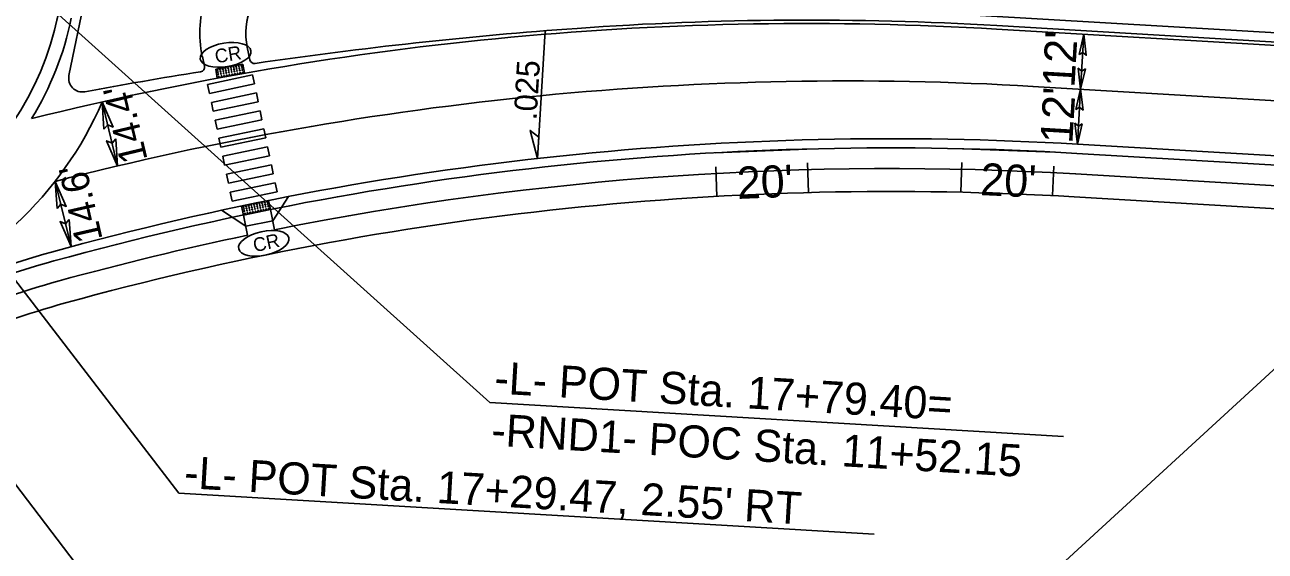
# Model space of a CAD drawing. Extents: x 2010838 to 2015151, y 441905 to 447792.
# Drawn here: x 2012023.9 to 2012294.2, y 444857.4 to 444972.1 of the extents above; entities that cross this region are included whole.
import ezdxf

# ---------------------------------------------------------------- set-up
doc = ezdxf.new("R2010")
doc.units = 0
for name, color, linetype in [('A-Wall-Blow', 7, 'Continuous'), ('A-Wall-Comp', 7, 'Continuous'), ('B-Sheet Number', 7, 'Continuous'), ('C-CURB STOPS', 7, 'Continuous'), ('C-Grave Plots', 7, 'Continuous'), ('CLRD', 7, 'Continuous'), ('Default_10ft_LIDAR_Contou', 7, 'Continuous'), ('HATCH', 7, 'Continuous'), ('s-Existing Major', 7, 'Continuous'), ('S-Existing Minor', 7, 'Continuous'), ('S-overhead electric', 7, 'Continuous'), ('TEXT-LG', 7, 'Continuous'), ('TEXT-MED', 7, 'Continuous'), ('X2', 7, 'Continuous'), ('X4', 7, 'Continuous')]:
    doc.layers.add(name, color=color, linetype=linetype)

msp = doc.modelspace()

# ---------------------------------------------------------------- linework, layer by layer
at = {"layer": 'A-Wall-Blow'}
msp.add_line((2012135.69, 444942.95), (2012137.33, 444970.78), dxfattribs=at)
at = {"layer": 'A-Wall-Comp'}
msp.add_lwpolyline([(2012135.69, 444942.95), (2012134.04, 444949.06), (2012135.96, 444947.57)], close=True, dxfattribs=at)
at = {"layer": 'B-Sheet Number'}
for p, q in [((2012174.5, 444941.15), (2012174.75, 444934.7)), ((2012194.49, 444941.97), (2012194.74, 444935.53)), ((2012228.17, 444942.04), (2012227.93, 444935.59)), ((2012248.16, 444941.3), (2012247.92, 444934.85))]:
    msp.add_line(p, q, dxfattribs=at)
at = {"layer": 'C-CURB STOPS'}
for p, q in [((2012033.57, 444961.05), (2012039.32, 444989.1)), ((2012235.76, 444971.9), (2012950.99, 444929.74)), ((2012062.64, 444965.14), (2012063.07, 444963.04)), ((2012072.42, 444967.19), (2012073, 444964.45))]:
    msp.add_line(p, q, dxfattribs=at)
for centre, radius, start, end in [((2012087.1, 444970.26), 25, 160.3361, 191.8302), ((2012087.1, 444970.26), 15, 157.4769, 191.8302), ((2012087.1, 444970.26), 15, 157.829, 191.8302), ((2012194.53, 444272.36), 700.75, 86.62643, 94.11232), ((2012213.12, 444013.78), 960, 94.11232, 98.32516), ((2012062.1, 444962.84), 1, 279.0417, 11.8302), ((2012073.98, 444964.65), 1, 191.8302, 278.3252), ((2012036.51, 444960.44), 3, 168.4243, 280.5677), ((2012213.12, 444013.78), 960, 99.0417, 100.56773)]:
    msp.add_arc(centre, radius, start, end, dxfattribs=at)
at = {"layer": 'CLRD'}
msp.add_line((2011239.41, 445032.63), (2013147.4, 444920.16), dxfattribs=at)
at = {"layer": 'Default_10ft_LIDAR_Contou'}
for p, q in [((2011967.46, 444987.16), (2012057.51, 444870.03)), ((2012125.28, 444889.75), (2012017.46, 444986.77)), ((2011971.99, 444937.37), (2012066.46, 444813.44)), ((2012250.31, 444882.38), (2012125.28, 444889.75)), ((2012057.51, 444870.03), (2012209.06, 444861.1))]:
    msp.add_line(p, q, dxfattribs=at)
at = {"layer": 'HATCH'}
for p, q in [((2012030.64, 444971.87), (2012048.37, 445045.09)), ((2012073.58, 444961.15), (2012063.79, 444959.1)), ((2012073.99, 444959.19), (2012073.58, 444961.15)), ((2012063.79, 444959.1), (2012064.2, 444957.14)), ((2012064.2, 444957.14), (2012073.99, 444959.19)), ((2012074.4, 444957.24), (2012064.61, 444955.18)), ((2012074.81, 444955.28), (2012074.4, 444957.24)), ((2012243.64, 444958.66), (2012959.89, 444916.44)), ((2012064.61, 444955.18), (2012065.02, 444953.23)), ((2012065.02, 444953.23), (2012074.81, 444955.28)), ((2012075.22, 444953.32), (2012065.43, 444951.27)), ((2012065.43, 444951.27), (2012065.84, 444949.31)), ((2012065.84, 444949.31), (2012075.63, 444951.36)), ((2012075.63, 444951.36), (2012075.22, 444953.32)), ((2012076.04, 444949.41), (2012066.25, 444947.35)), ((2012076.45, 444947.45), (2012076.04, 444949.41)), ((2012066.25, 444947.35), (2012066.66, 444945.4)), ((2012066.66, 444945.4), (2012076.45, 444947.45)), ((2012076.86, 444945.49), (2012067.07, 444943.44)), ((2012067.07, 444943.44), (2012067.48, 444941.48)), ((2012067.48, 444941.48), (2012077.27, 444943.53)), ((2012077.27, 444943.53), (2012076.86, 444945.49)), ((2012077.68, 444941.57), (2012067.89, 444939.52)), ((2012078.09, 444939.62), (2012077.68, 444941.57)), ((2012067.89, 444939.52), (2012068.3, 444937.57)), ((2012068.3, 444937.57), (2012078.09, 444939.62)), ((2012078.5, 444937.66), (2012068.71, 444935.61)), ((2012068.71, 444935.61), (2012069.12, 444933.65)), ((2012069.12, 444933.65), (2012078.91, 444935.7)), ((2012078.91, 444935.7), (2012078.5, 444937.66))]:
    msp.add_line(p, q, dxfattribs=at)
msp.add_circle((2011967.46, 444987.16), 65, dxfattribs=at)
for centre, radius, start, end in [((2012203.04, 444269.86), 690, 86.62643, 104.47814), ((2011967.46, 444987.16), 80, 242.6645, 336.5135)]:
    msp.add_arc(centre, radius, start, end, dxfattribs=at)
at = {"layer": 's-Existing Major'}
for points in [[(2012253.69, 444965.58), (2012254.73, 444970.03), (2012255.26, 444965.46), (2012254.5, 444966.08)], [(2012255.06, 444962.49), (2012254.03, 444958.05), (2012253.49, 444962.61), (2012254.26, 444961.99)], [(2012252.99, 444953.6), (2012254.03, 444958.05), (2012254.56, 444953.48), (2012253.79, 444954.1)], [(2012041.2, 444949.36), (2012040.84, 444955.28), (2012043.2, 444949.8), (2012042.02, 444950.28)], [(2012254.36, 444950.52), (2012253.32, 444946.07), (2012252.79, 444950.63), (2012253.55, 444950.01)], [(2012043.78, 444947.24), (2012044.14, 444941.31), (2012041.78, 444946.8), (2012042.96, 444946.31)], [(2012030.97, 444932.02), (2012030.53, 444937.94), (2012032.96, 444932.49), (2012031.77, 444932.96)], [(2012033.63, 444929.66), (2012034.07, 444923.74), (2012031.64, 444929.19), (2012032.83, 444928.72)]]:
    msp.add_lwpolyline(points, close=True, dxfattribs=at)
at = {"layer": 'S-Existing Minor'}
for p, q in [((2012254.73, 444970.03), (2012254.03, 444958.05)), ((2012254.03, 444958.05), (2012253.32, 444946.07)), ((2012040.84, 444955.28), (2012044.14, 444941.31)), ((2012030.53, 444937.94), (2012034.07, 444923.74)), ((2011915.11, 444547.35), (2012331.51, 444929.43))]:
    msp.add_line(p, q, dxfattribs=at)
at = {"layer": 'S-overhead electric'}
for p, q in [((2012235.72, 444971.15), (2012960.59, 444928.42)), ((2012253.32, 444946.07), (2012350.58, 444940.34))]:
    msp.add_line(p, q, dxfattribs=at)
for centre, radius, start, end in [((2011967.46, 444987.16), 68, 328.4998, 348.4243), ((2012194.53, 444272.36), 700, 86.62643, 103.97797), ((2012212.72, 444257.26), 690, 86.62643, 105.37852), ((2012078.79, 444744.18), 185, 105.3785, 113.9163)]:
    msp.add_arc(centre, radius, start, end, dxfattribs=at)
at = {"layer": 'TEXT-LG'}
for p, q in [((2012065.54, 444962.41), (2012071.44, 444963.49)), ((2012065.9, 444960.44), (2012065.54, 444962.41)), ((2012071.44, 444963.49), (2012071.8, 444961.52)), ((2012065.9, 444960.44), (2012071.8, 444961.52)), ((2012252.94, 444939.58), (2012365.39, 444932.95)), ((2012071.18, 444932.59), (2012077.06, 444933.8)), ((2012071.59, 444930.63), (2012071.18, 444932.59)), ((2012077.06, 444933.8), (2012077.46, 444931.84)), ((2012081.44, 444934.66), (2012077.97, 444929.39)), ((2012252.64, 444934.59), (2012370.88, 444927.62)), ((2012066.81, 444931.66), (2012072.09, 444928.18)), ((2012071.58, 444930.63), (2012077.46, 444931.84)), ((2012071.59, 444930.63), (2012072.49, 444926.23)), ((2012077.46, 444931.84), (2012078.37, 444927.43)), ((2012072.09, 444928.18), (2012077.97, 444929.39))]:
    msp.add_line(p, q, dxfattribs=at)
for centre in [(2012065.96, 444962.18), (2012066.52, 444962.28), (2012067.12, 444962.39), (2012067.2, 444961.97), (2012067.68, 444962.49), (2012067.77, 444962.07), (2012068.27, 444962.6), (2012068.36, 444962.18), (2012068.87, 444962.71), (2012068.96, 444962.29), (2012069.46, 444962.81), (2012069.55, 444962.39), (2012069.62, 444961.94), (2012070.02, 444962.92), (2012070.11, 444962.5), (2012070.19, 444962.04), (2012070.62, 444963.02), (2012070.7, 444962.6), (2012070.78, 444962.15), (2012071.18, 444963.12), (2012071.27, 444962.7), (2012071.34, 444962.25), (2012066.05, 444961.76), (2012066.12, 444961.31), (2012066.23, 444960.76), (2012066.61, 444961.86), (2012066.69, 444961.41), (2012066.8, 444960.87), (2012067.28, 444961.51), (2012067.39, 444960.97), (2012067.84, 444961.62), (2012067.95, 444961.07), (2012068.43, 444961.72), (2012068.54, 444961.18), (2012069.03, 444961.83), (2012069.14, 444961.29), (2012069.73, 444961.4), (2012070.3, 444961.5), (2012070.89, 444961.6), (2012071.45, 444961.71), (2012071.61, 444932.38), (2012072.17, 444932.49), (2012072.76, 444932.61), (2012072.86, 444932.19), (2012073.32, 444932.72), (2012073.42, 444932.3), (2012073.91, 444932.84), (2012074.01, 444932.42), (2012074.51, 444932.97), (2012074.6, 444932.55), (2012075.1, 444933.08), (2012075.19, 444932.67), (2012075.28, 444932.21), (2012075.66, 444933.2), (2012075.76, 444932.78), (2012075.84, 444932.33), (2012076.25, 444933.32), (2012076.34, 444932.9), (2012076.43, 444932.45), (2012076.81, 444933.43), (2012076.91, 444933.01), (2012076.99, 444932.56), (2012071.71, 444931.96), (2012071.79, 444931.51), (2012071.91, 444930.96), (2012072.27, 444932.07), (2012072.36, 444931.62), (2012072.48, 444931.08), (2012072.94, 444931.74), (2012073.06, 444931.2), (2012073.51, 444931.85), (2012073.63, 444931.31), (2012074.1, 444931.97), (2012074.21, 444931.43), (2012074.69, 444932.1), (2012074.81, 444931.55), (2012075.4, 444931.67), (2012075.96, 444931.79), (2012076.55, 444931.91), (2012077.11, 444932.02)]:
    msp.add_circle(centre, 0.0869, dxfattribs=at)
for centre, radius, start, end in [((2012212.72, 444257.26), 683.5, 86.62643, 101.33591), ((2012212.72, 444257.26), 678.5, 86.62643, 105.37852), ((2012212.72, 444257.26), 683.5, 101.83883, 105.37852), ((2012078.79, 444744.18), 178.5, 105.3785, 113.9163), ((2012078.79, 444744.18), 173.5, 105.3785, 113.9163)]:
    msp.add_arc(centre, radius, start, end, dxfattribs=at)
at = {"layer": 'TEXT-MED'}
msp.add_line((2012253.2, 444944.07), (2012350.46, 444938.34), dxfattribs=at)
for centre, radius, start, end in [((2012212.72, 444257.26), 688, 86.62643, 105.37852), ((2012078.79, 444744.18), 183, 105.3785, 113.9163)]:
    msp.add_arc(centre, radius, start, end, dxfattribs=at)
at = {"layer": 'X2'}
for p, q in [((2012194.36, 444944.97), (2012174.38, 444944.15)), ((2012248.27, 444944.3), (2012228.28, 444945.04))]:
    msp.add_line(p, q, dxfattribs=at)
at = {"layer": 'X4'}
for centre, major_axis in [((2012067.7, 444965.52), (5.53, 0.9)), ((2012076.03, 444924.46), (5.48, 1.21))]:
    msp.add_ellipse(centre, major_axis=major_axis, ratio=0.462467, dxfattribs=at)

# ---------------------------------------------------------------- texts
at = {"layer": 'A-Wall-Blow'}
msp.add_text('.025', height=5, rotation=86.6264, dxfattribs=at).set_placement((2012135.46, 444951.23))
at = {"layer": 'C-Grave Plots'}
for s, height, rotation, p in [("12'", 7, 86.6264, (2012252.67, 444958.31)), ("14.4'", 6, 103.4479, (2012050.74, 444942.72)), ("12'", 7, 86.6264, (2012252.21, 444946.08)), ("14.6'", 6, 102.8719, (2012040.94, 444925.36)), ("20'", 7, 2.3257, (2012179.25, 444934.12)), ("20'", 7, 357.3485, (2012232.03, 444934.98))]:
    msp.add_text(s, height=height, rotation=rotation, dxfattribs=at).set_placement(p)
at = {"layer": 'Default_10ft_LIDAR_Contou'}
for s, p in [('-L- POT Sta. 17+79.40=', (2012126.15, 444891.75)), ('-RND1- POC Sta. 11+52.15', (2012125.48, 444880.39)), ("-L- POT Sta. 17+29.47, 2.55' RT", (2012058.54, 444871.14))]:
    msp.add_text(s, height=7, rotation=356.6264, dxfattribs=at).set_placement(p)
at = {"layer": 'X4'}
for rotation, p in [(9.2662, (2012065.61, 444963.68)), (12.4109, (2012074.05, 444922.51))]:
    msp.add_text('CR', height=3, rotation=rotation, dxfattribs=at).set_placement(p)

doc.saveas('drawing.dxf')
